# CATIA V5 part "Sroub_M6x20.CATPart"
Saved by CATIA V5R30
Part number: Sroub_M6x20
Nomenclature: E1220/6/20
Description: MEUSBURGER
Publications: "DrillHole", "TapHole", "Base"
Bounding box of the stored display mesh (mm): x -5.992 to 5.992, y -5.992 to 5.992, z -3.3 to 16.7
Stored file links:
  E:\Bakalarka\Model\Forma_v7\Sroub_M6x20.CATPart
  E:\dev\MoldDesign\intel_a\startup\components\MoldCatalog\CountersunkScrew\Meusburger\CountersunkScrew_E1220\TableE1220.txt
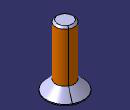
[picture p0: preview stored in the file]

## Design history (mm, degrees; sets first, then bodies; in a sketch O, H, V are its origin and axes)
Parameters
  Ref = "E1220/6/20" {design table}
  D = 6 mm {design table}
  D1 = 6 mm {design table}
  D3 = 12 mm {design table}
  L = 20 mm {design table}
  L3 = 3.3 mm {design table}
  SW = 4 mm {design table}
  L1 = 0.3 mm {design table}
  L4 = 2.5 mm {design table}
  d2kern = 4.77 mm {design table}
  F = 0.615 mm {design table}
  W = 90 deg {design table}
  kd1 = 6.6 mm {design table}
  kl1 = 14 mm {design table}
  kl = 25 mm {design table}
  dkern = 4.92 mm {design table}
  C = 5 mm {design table}
  ThreadString = "M6" {design table}
  Mat = "" {design table}
  HeatTreat = "" {design table}
  SupplierRef = "Meusburger 2017"
  BmpRef = "F_MldCountersunkScrew_D_L"
  DrillHole_Length = 225 mm
  HeadThick = 3.3 mm {= L3}
  HeadDiam = 12 mm {= D3}
  ScrewThread = 16.7 mm {= Thread1.Depth}
  ScrewPitch = 1 mm {= Thread1.Pitch}
Set1 "BaseBody"
  Point1 "Base": (0, 0, 0)
  Plane1: type Offset, RefPlane face of Shaft1 from Sketch1.L1, Offset 225 {= DrillHole_Length}, reversed
Body1 "PartBody" (main body)
  Sketch1 on yz-plane, origin (0, 0, 0), H (0, 0, -1), V (0, 1, 0)
    point P1 (3.3, 0)
    line L1 (3.3, 0) -> (3.3, -6)
    point P2 (3.3, -6)
    point P3 (-16.7, -3)
    point P4 (-16.7, -3)
    line L2 (-16.7, -3) -> (-16.7, 0)
    point P5 (-16.7, 0)
    point P6 (-16.7, 0)
    axis line L3 (-16.7, 0) -> (3.3, 0)
    point P7 (3.3, 0)
    point P8 (0, -3)
    line L4 (0, -3) -> (-16.7, -3)
    point P9 (0, -3)
    line L5 (0, -3) -> (3, -6)
    line L6 (3, -6) -> (3.3, -6)
    distance L1 L2 = 20 {= L}
    distance L4 L3 = 3 {= D /2}
    length L1 = 6 {= D3 /2}
    distance P9 P2 H = 3.3 {= L3}
    angle L5 L6 = 45 {= W/2}
    coincidence: P5 L3, P1 L3, L3 H, P4 P3, P9 P8, P6 L2, P7 L1, V P8
    vertical: L1 V, L2 V
    horizontal: L4 H, L6 H
  Shaft1: profile Sketch1, axis Sketch1.L3, angle 360
  Sketch2 on face of Shaft1 from Sketch1.L1, origin (0, 0, -3.3), H (1, 0, 0), V (0, -1, 0)
    point P1 (1.1547, 2)
    point P2 (-1.1547, 2)
    point P3 (-2.3094, 0)
    point P4 (-1.1547, -2)
    point P5 (1.1547, -2)
    point P6 (2.3094, 0)
    point P7 (0, 2)
    line L1 (1.1547, 2) -> (-1.1547, 2)
    line L2 (-1.1547, 2) -> (-2.3094, 0)
    line L3 (-2.3094, 0) -> (-1.1547, -2)
    line L4 (-1.1547, -2) -> (1.1547, -2)
    line L5 (1.1547, -2) -> (2.3094, 0)
    line L6 (2.3094, 0) -> (1.1547, 2)
    construction line L7 (0, 0) -> (0, 2)
    construction circle A1 centre (0, 0) radius 2.3094
    construction arc A2 centre (1.1547, -2) radius 2.3094 from (-1.1547, -2) to (2.3094, 0) cw
    construction arc A3 centre (-1.1547, 2) radius 2.3094 from (-2.3094, 0) to (1.1547, 2) ccw
    point P8 (1.1547, -2)
    point P9 (-1.1547, 2)
    distance L1 L4 = 4 {= SW}
    vertical: L7 V
    coincidence: A1 P1, A1 P2, A1 P3, A1 P4, A1 P5, A1 P6, A2 P4, A2 P6, A2 O, P8 P5, A3 P3, A3 P1, A3 O, P9 P2
    midpoint: P7 L1
  Pocket1: profile Sketch2, direction (0, 0, 1), length 1.65 {= L3 /2}
  Thread1: "M6", diameter 6, depth 16.7 {= L-L3}, pitch 1, on face of Shaft1 from Sketch1.L4, from face of Shaft1 from Sketch1.L2
  Chamfer1: length 0.615 {= F}, angle 45, on edge [face of Shaft1 from Sketch1.L2 | face of Shaft1 from Sketch1.L4]
Body2 "DrillHole"
  Sketch3 on Plane1, origin (0, 0, -228.3), H (1, 0, 0), V (0, 1, 0)
    point P1 (0, 0)
    reference projected circle E1 centre (0, 0) radius 6 from edge [face of Shaft1 from Sketch1.L5 | face of Shaft1 from Sketch1.L6]
    concentricity: P1 E1
  Hole1: placed by Sketch3, at (0, 0, -228.3) direction (0, 0, 1), diameter 6.6 {= kd1}, depth 245 {= DrillHole_Length +L}, type CounterDrilledType, Diameter 6.6 {= kd1}, DiameterThread 11, Pas 1, Profile a sketch, Sketch Sketch3, ThreadDepth 10, Angle 90, Depth 225.3 {= DrillHole_Length +L1}, Diameter 12 {= D3}
Body3 "TapHole"
  Sketch4 on Plane1, origin (0, 0, -228.3), H (1, 0, 0), V (0, 1, 0)
    point P1 (0, 0)
    reference projected circle E1 centre (0, 0) radius 6 from edge [face of Shaft1 from Sketch1.L5 | face of Shaft1 from Sketch1.L6]
    concentricity: E1 P1
  Hole2: placed by Sketch4, at (0, 0, -228.3) direction (0, 0, 1), diameter 4.917, depth 250 {= DrillHole_Length +kl}, V-bottom angle 90, threaded "M6", thread diameter 6, thread depth 250 {= DrillHole_Length +kl}, pitch 1
Relations
  design table "TableE1220", configuration 34, drives Ref, D, D1, D3, L, L3, SW, L1, L4, d2kern, F, W, kd1, kl1, kl, dkern, C, ThreadString, Mat, HeatTreat
  Thread1.ThreadDescription = ThreadString
  Hole2.ThreadDescription = ThreadString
